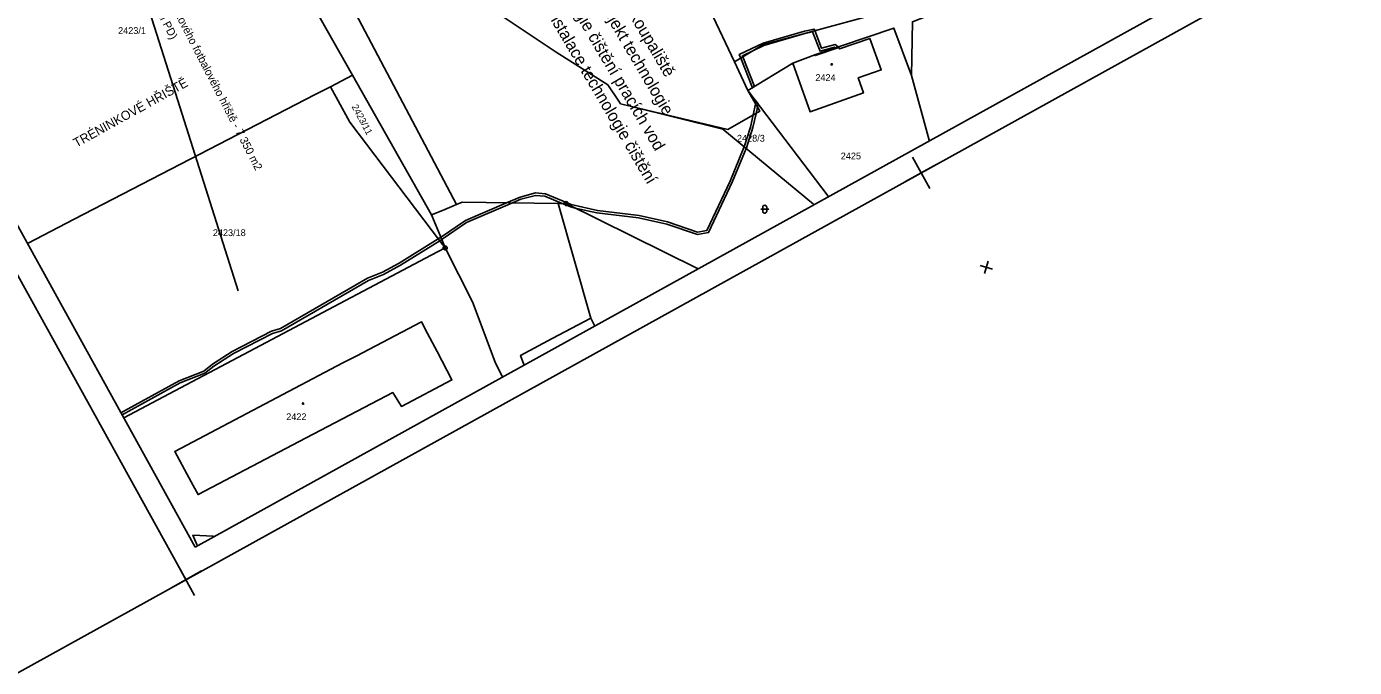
# Model space of a CAD drawing. Extents: x -483721 to -481876, y -1129170 to -1127366.
# Drawn here: x -482470.6 to -482138.7, y -1128476.5 to -1128316.3 of the extents above; entities that cross this region are included whole.
import ezdxf

# ---------------------------------------------------------------- set-up
doc = ezdxf.new("R2010")
doc.units = 0
for name, color, linetype in [('Hranice parcel', 7, 'Continuous'), ('Parcelní čísla', 7, 'Continuous'), ('u_návrh_popis', 7, 'Continuous'), ('u_OP_lesa', 7, 'Continuous'), ('u_SO_POPIS_1000', 7, 'Continuous'), ('u_vytyčení', 7, 'Continuous'), ('Věcná břemena k části', 7, 'Continuous'), ('x_formát_křížky', 7, 'Continuous'), ('x_formát_rám', 7, 'Continuous'), ('x_rozpiska', 7, 'Continuous'), ('Značky bodu BP', 7, 'Continuous'), ('Značky budov', 7, 'Continuous'), ('Značky kultur', 7, 'Continuous')]:
    doc.layers.add(name, color=color, linetype=linetype)

msp = doc.modelspace()

# ---------------------------------------------------------------- linework, layer by layer
for p, q in [((-482430.72, -1128454.53), (-482654.9, -1128049.38)), ((-482428.38, -1128446.38), (-482646.74, -1128051.72)), ((-481887.63, -1128147.18), (-482428.38, -1128446.38))]:
    msp.add_line(p, q)
at = {"layer": 'Hranice parcel'}
for p, q in [((-482389.07, -1128311.59), (-482363.13, -1128360.82)), ((-482273.58, -1128323.42), (-482279.08, -1128325.47)), ((-482293.58, -1128325.11), (-482290.26, -1128332.27)), ((-482279.08, -1128325.47), (-482290.26, -1128332.27)), ((-482394.61, -1128331.34), (-482389.1, -1128328.49)), ((-482369.34, -1128363.37), (-482389.1, -1128328.49)), ((-482244.98, -1128344.72), (-482249.37, -1128328.52)), ((-482290.26, -1128332.27), (-482270.22, -1128358.69)), ((-482337.66, -1128360.53), (-482335.69, -1128360.54)), ((-482329.54, -1128389.19), (-482337.66, -1128360.53))]:
    msp.add_line(p, q, dxfattribs=at)
for points in [[(-482389.1, -1128328.49), (-482425.67, -1128263.94), (-482430.69, -1128257.73)], [(-482293.58, -1128325.11), (-482308.82, -1128293.03), (-482316.72, -1128296.54), (-482327.19, -1128273.95)], [(-482200.01, -1128286.72), (-482200.72, -1128288.87), (-482200.21, -1128290.43), (-482227.75, -1128301.03), (-482261.08, -1128313.93), (-482286.52, -1128320.87), (-482293.58, -1128325.11)], [(-482249.37, -1128328.52), (-482249.15, -1128315.12), (-482198.82, -1128295.4), (-482196.63, -1128298.38)], [(-482319.32, -1128336.33), (-482322.09, -1128335.61), (-482322.54, -1128334.96), (-482325.31, -1128330.9), (-482338.21, -1128322.74), (-482352.22, -1128313.35), (-482355.77, -1128304.09)], [(-482249.37, -1128328.52), (-482253.8, -1128316.68), (-482273.58, -1128323.42)], [(-482273.58, -1128323.42), (-482273.49, -1128323.58), (-482267.57, -1128321.56), (-482267.41, -1128321.92), (-482259.76, -1128319.26), (-482256.96, -1128327.14), (-482262.67, -1128329.17), (-482261.38, -1128332.89), (-482274.72, -1128337.6), (-482279.08, -1128325.47)], [(-482470.36, -1128370.5), (-482458.69, -1128364.47), (-482398.41, -1128333.3), (-482394.61, -1128331.34)], [(-482394.61, -1128331.34), (-482389.79, -1128340.19), (-482367.06, -1128370.14), (-482365.93, -1128371.63)], [(-482290.26, -1128332.27), (-482287.31, -1128337.5), (-482295.32, -1128342.01), (-482319.32, -1128336.33)], [(-482273.9, -1128360.72), (-482296.55, -1128341.96), (-482319.32, -1128336.33)], [(-482363.13, -1128360.82), (-482366.6, -1128362.25), (-482369.34, -1128363.37)], [(-482365.93, -1128371.63), (-482366.8, -1128369.52), (-482369.34, -1128363.37)], [(-482337.66, -1128360.53), (-482361.72, -1128360.24), (-482363.13, -1128360.82)], [(-482335.69, -1128360.54), (-482302.9, -1128376.77)], [(-482365.93, -1128371.63), (-482369.43, -1128373.46), (-482446.25, -1128414.08)], [(-482351.71, -1128403.78), (-482353.45, -1128400.22), (-482359.12, -1128385.09), (-482365.93, -1128371.63)], [(-482346.29, -1128400.77), (-482347.1, -1128398.51), (-482339.17, -1128394.29), (-482329.54, -1128389.19)], [(-482329.54, -1128389.19), (-482329.22, -1128389.83), (-482328.63, -1128391)], [(-482428.93, -1128430.98), (-482427.69, -1128433.26), (-482402.4, -1128420.02), (-482379.01, -1128407.77), (-482376.85, -1128411.24), (-482364.26, -1128404.64), (-482367.96, -1128397.56), (-482370.32, -1128393.05), (-482371.87, -1128390.08), (-482388.2, -1128398.67), (-482391.47, -1128400.38), (-482433.53, -1128422.5), (-482430.52, -1128428.05), (-482428.93, -1128430.98)], [(-482427.88, -1128445.92), (-482427.97, -1128445.75), (-482428.98, -1128443.45), (-482423.86, -1128443.7)]]:
    msp.add_lwpolyline(points, dxfattribs=at)
at = {"layer": 'u_OP_lesa'}
msp.add_lwpolyline([(-482417.65, -1128382.4), (-482432.28, -1128336.35), (-482451.92, -1128274.51), (-482459.73, -1128242.32), (-482439.86, -1128216.05), (-482430.66, -1128194.68), (-482468, -1128132.41)], dxfattribs=at)
at = {"layer": 'u_vytyčení'}
for p, q in [((-482229.14, -1128376.93), (-482232.19, -1128376.05)), ((-482230.22, -1128374.96), (-482231.1, -1128378.02))]:
    msp.add_line(p, q, dxfattribs=at)
at = {"layer": 'Věcná břemena k části'}
msp.add_lwpolyline([(-482288.86, -1128322.28), (-482286.29, -1128321.05), (-482276.02, -1128318.01), (-482274.09, -1128317.64), (-482272.24, -1128322.47), (-482268.62, -1128321.49), (-482268.39, -1128321.65), (-482267.69, -1128321.41), (-482268.5, -1128320.83), (-482271.88, -1128321.75), (-482273.57, -1128317.34), (-482273.71, -1128316.96), (-482276.16, -1128317.43), (-482286.49, -1128320.48), (-482292.42, -1128323.31), (-482292.07, -1128324.2), (-482289.14, -1128331.59), (-482288.62, -1128331.28), (-482291.55, -1128323.89), (-482291.66, -1128323.61)], close=True, dxfattribs=at)
msp.add_lwpolyline([(-482446.66, -1128413.34), (-482432.15, -1128405.37), (-482425.98, -1128402.92), (-482423.77, -1128401.16), (-482418.83, -1128398.02), (-482409.1, -1128393.01), (-482406.87, -1128392.35), (-482385.08, -1128379.75), (-482381.31, -1128378.26), (-482377.11, -1128375.97), (-482367.29, -1128369.83), (-482366.8, -1128369.52), (-482366.66, -1128369.43), (-482360.56, -1128365.28), (-482349.09, -1128360.39), (-482346.98, -1128359.49), (-482343.33, -1128358.5), (-482341.02, -1128358.73), (-482336.69, -1128360.53), (-482334.62, -1128361.4), (-482333.4, -1128361.67), (-482328, -1128362.9), (-482317.58, -1128364.15), (-482310.51, -1128365.69), (-482302.9, -1128368.28), (-482300.09, -1128367.79), (-482294.2, -1128355.17), (-482290.71, -1128346.79), (-482290.63, -1128346.6), (-482289.01, -1128341.58), (-482288.22, -1128338.01), (-482287.89, -1128336.48), (-482287.7, -1128335.64), (-482288.28, -1128334.87), (-482288.24, -1128335.31), (-482288.33, -1128335.7), (-482288.93, -1128338.41), (-482289.59, -1128341.42), (-482291.21, -1128346.38), (-482291.26, -1128346.55), (-482294.74, -1128354.93), (-482300.51, -1128367.25), (-482302.86, -1128367.66), (-482310.36, -1128365.11), (-482317.48, -1128363.55), (-482327.9, -1128362.3), (-482334.44, -1128360.82), (-482340.88, -1128358.15), (-482343.39, -1128357.9), (-482347.18, -1128358.93), (-482350.58, -1128360.37), (-482360.86, -1128364.76), (-482366.83, -1128368.86), (-482367.02, -1128368.98), (-482367.65, -1128369.37), (-482377.41, -1128375.45), (-482381.57, -1128377.72), (-482385.34, -1128379.21), (-482407.11, -1128391.79), (-482409.32, -1128392.45), (-482419.13, -1128397.5), (-482424.11, -1128400.68), (-482426.28, -1128402.4), (-482432.41, -1128404.83), (-482446.95, -1128412.81)], dxfattribs=at)
at = {"layer": 'x_formát_křížky'}
for p, q in [((-482249.15, -1128348.93), (-482244.8, -1128356.8)), ((-482250.91, -1128355.04), (-482243.04, -1128350.69)), ((-482434.66, -1128456.71), (-482426.79, -1128452.35)), ((-482432.9, -1128450.6), (-482428.55, -1128458.47))]:
    msp.add_line(p, q, dxfattribs=at)
at = {"layer": 'x_formát_rám'}
msp.add_line((-481879.48, -1128149.53), (-483716.96, -1129166.21), dxfattribs=at)
at = {"layer": 'Značky bodu BP'}
for centre, radius in [((-482335.69, -1128360.54), 0.5), ((-482335.69, -1128360.54), 0.0303), ((-482365.93, -1128371.63), 0.5), ((-482365.93, -1128371.63), 0.0303)]:
    msp.add_circle(centre, radius, dxfattribs=at)
at = {"layer": 'Značky budov'}
for centre in [(-482269.31, -1128325.77), (-482401.45, -1128410.52)]:
    msp.add_circle(centre, 0.175, dxfattribs=at)
at = {"layer": 'Značky kultur'}
for p, q in [((-482287.07, -1128361.96), (-482285.07, -1128361.96)), ((-482286.57, -1128361.46), (-482286.57, -1128362.46)), ((-482285.57, -1128362.46), (-482285.57, -1128361.46))]:
    msp.add_line(p, q, dxfattribs=at)
for centre, start, end in [((-482286.07, -1128361.46), 0, 180), ((-482286.07, -1128362.46), 180, 359.9879)]:
    msp.add_arc(centre, 0.5, start, end, dxfattribs=at)

# ---------------------------------------------------------------- texts
at = {"layer": 'Parcelní čísla'}
for s, p in [('2423/1', (-482447.67, -1128318.17)), ('2424', (-482273.41, -1128329.92)), ('2428/3', (-482293, -1128345.08)), ('2425', (-482267.06, -1128349.51)), ('2423/18', (-482423.99, -1128368.68)), ('2422', (-482405.65, -1128414.67))]:
    msp.add_text(s, height=1.7, dxfattribs=at).set_placement(p)
msp.add_text('2423/11', height=1.7, rotation=298, dxfattribs=at).set_placement((-482389.35, -1128336.32))
at = {"layer": 'u_návrh_popis'}
for s, p in [('(není součástí PD)', (-482444.64, -1128300.07)), ('závlaha tréninkového fotbalového hřiště - 7 350 m2', (-482441.1, -1128298.58))]:
    msp.add_text(s, height=2, rotation=297.2992, dxfattribs=at).set_placement(p)
at = {"layer": 'u_SO_POPIS_1000'}
for s, p in [('SO 02 - Prací vody z koupaliště', (-482339.31, -1128280.81)), ('SO 07 - Provozní objekt technologie', (-482343.78, -1128283.38)), ('PS 01 - Technologie čištění pracích vod', (-482349.34, -1128286.54)), ('PS 02 - Elektroinstalace technologie čištění', (-482354.45, -1128289.48))]:
    msp.add_text(s, height=3, rotation=300.4806, dxfattribs=at).set_placement(p)
at = {"layer": 'x_rozpiska'}
msp.add_text('TRÉNINKOVÉ HŘIŠTĚ', height=2.3, rotation=28.9559, dxfattribs=at).set_placement((-482458.08, -1128346.61))

doc.saveas('drawing.dxf')
